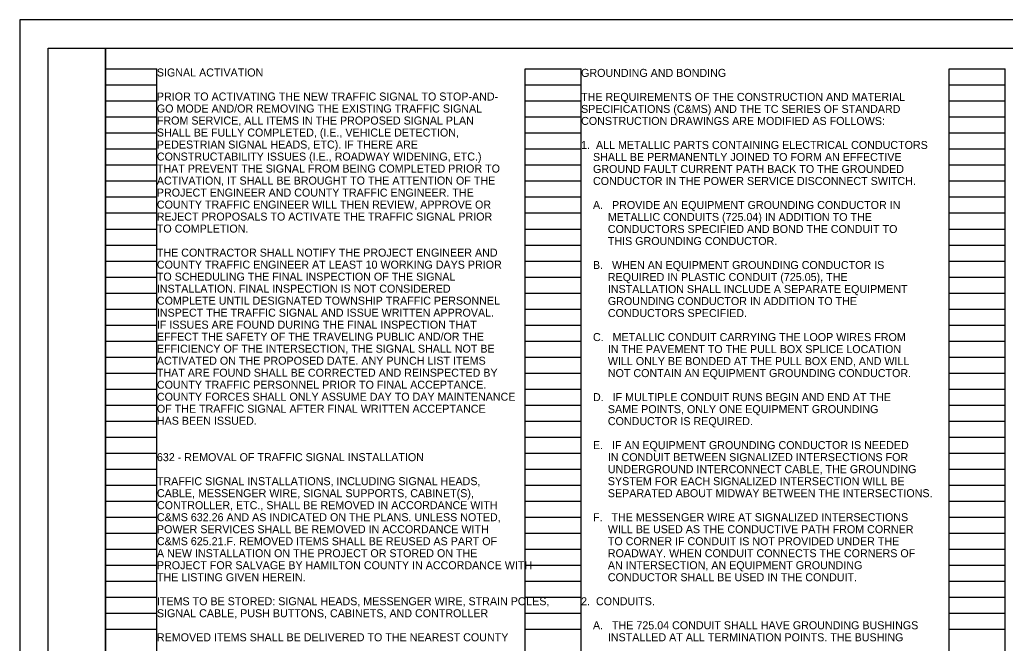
# Model space of a CAD drawing. Extents: x 0 to 34, y 0 to 22.
# Drawn here: x 0 to 17.24, y 11.1 to 22 of the extents above; entities that cross this region are included whole.
import ezdxf

# ---------------------------------------------------------------- set-up
doc = ezdxf.new("R2010")
doc.units = 0
for name, color, linetype in [('SH_Border', 7, 'Continuous'), ('SH_Cut_Line', 7, 'Continuous'), ('SH_Data', 7, 'Continuous'), ('SH_Text', 7, 'Continuous')]:
    doc.layers.add(name, color=color, linetype=linetype)

msp = doc.modelspace()

# ---------------------------------------------------------------- linework, layer by layer
at = {"layer": 'SH_Border'}
for points in [[(0.5, 21.5), (1.5, 21.5), (1.5, 0.5), (0.5, 0.5)], [(1.5, 21.5), (33.5, 21.5), (33.5, 0.5), (1.5, 0.5)]]:
    msp.add_lwpolyline(points, close=True, dxfattribs=at)
at = {"layer": 'SH_Cut_Line'}
msp.add_lwpolyline([(0, 0), (34, 0), (34, 22), (0, 22)], close=True, dxfattribs=at)
at = {"layer": 'SH_Data'}
for p, q in [((1.5, 0.98), (1.5, 21.14)), ((1.5, 21.14), (2.4, 21.14)), ((2.4, 0.98), (2.4, 21.14)), ((8.84, 0.98), (8.84, 21.14)), ((8.84, 21.14), (9.82, 21.14)), ((9.82, 0.98), (9.82, 21.14)), ((16.26, 0.98), (16.26, 21.14)), ((16.26, 21.14), (17.24, 21.14)), ((17.24, 0.98), (17.24, 21.14)), ((1.5, 20.86), (2.4, 20.86)), ((8.84, 20.86), (9.82, 20.86)), ((16.26, 20.86), (17.24, 20.86)), ((1.5, 20.58), (2.4, 20.58)), ((8.84, 20.58), (9.82, 20.58)), ((16.26, 20.58), (17.24, 20.58)), ((1.5, 20.3), (2.4, 20.3)), ((8.84, 20.3), (9.82, 20.3)), ((16.26, 20.3), (17.24, 20.3)), ((1.5, 20.02), (2.4, 20.02)), ((8.84, 20.02), (9.82, 20.02)), ((16.26, 20.02), (17.24, 20.02)), ((1.5, 19.74), (2.4, 19.74)), ((8.84, 19.74), (9.82, 19.74)), ((16.26, 19.74), (17.24, 19.74)), ((1.5, 19.46), (2.4, 19.46)), ((8.84, 19.46), (9.82, 19.46)), ((16.26, 19.46), (17.24, 19.46)), ((1.5, 19.18), (2.4, 19.18)), ((8.84, 19.18), (9.82, 19.18)), ((16.26, 19.18), (17.24, 19.18)), ((1.5, 18.9), (2.4, 18.9)), ((8.84, 18.9), (9.82, 18.9)), ((16.26, 18.9), (17.24, 18.9)), ((1.5, 18.62), (2.4, 18.62)), ((8.84, 18.62), (9.82, 18.62)), ((16.26, 18.62), (17.24, 18.62)), ((1.5, 18.34), (2.4, 18.34)), ((8.84, 18.34), (9.82, 18.34)), ((16.26, 18.34), (17.24, 18.34)), ((1.5, 18.06), (2.4, 18.06)), ((8.84, 18.06), (9.82, 18.06)), ((16.26, 18.06), (17.24, 18.06)), ((1.5, 17.78), (2.4, 17.78)), ((8.84, 17.78), (9.82, 17.78)), ((16.26, 17.78), (17.24, 17.78)), ((1.5, 17.5), (2.4, 17.5)), ((8.84, 17.5), (9.82, 17.5)), ((16.26, 17.5), (17.24, 17.5)), ((1.5, 17.22), (2.4, 17.22)), ((8.84, 17.22), (9.82, 17.22)), ((16.26, 17.22), (17.24, 17.22)), ((1.5, 16.94), (2.4, 16.94)), ((8.84, 16.94), (9.82, 16.94)), ((16.26, 16.94), (17.24, 16.94)), ((1.5, 16.66), (2.4, 16.66)), ((8.84, 16.66), (9.82, 16.66)), ((16.26, 16.66), (17.24, 16.66)), ((1.5, 16.38), (2.4, 16.38)), ((8.84, 16.38), (9.82, 16.38)), ((16.26, 16.38), (17.24, 16.38)), ((1.5, 16.1), (2.4, 16.1)), ((8.84, 16.1), (9.82, 16.1)), ((16.26, 16.1), (17.24, 16.1)), ((1.5, 15.82), (2.4, 15.82)), ((8.84, 15.82), (9.82, 15.82)), ((16.26, 15.82), (17.24, 15.82)), ((1.5, 15.54), (2.4, 15.54)), ((8.84, 15.54), (9.82, 15.54)), ((16.26, 15.54), (17.24, 15.54)), ((1.5, 15.26), (2.4, 15.26)), ((8.84, 15.26), (9.82, 15.26)), ((16.26, 15.26), (17.24, 15.26)), ((1.5, 14.98), (2.4, 14.98)), ((8.84, 14.98), (9.82, 14.98)), ((16.26, 14.98), (17.24, 14.98)), ((1.5, 14.7), (2.4, 14.7)), ((8.84, 14.7), (9.82, 14.7)), ((16.26, 14.7), (17.24, 14.7)), ((1.5, 14.42), (2.4, 14.42)), ((8.84, 14.42), (9.82, 14.42)), ((16.26, 14.42), (17.24, 14.42)), ((1.5, 14.14), (2.4, 14.14)), ((8.84, 14.14), (9.82, 14.14)), ((16.26, 14.14), (17.24, 14.14)), ((1.5, 13.86), (2.4, 13.86)), ((8.84, 13.86), (9.82, 13.86)), ((16.26, 13.86), (17.24, 13.86)), ((1.5, 13.58), (2.4, 13.58)), ((8.84, 13.58), (9.82, 13.58)), ((16.26, 13.58), (17.24, 13.58)), ((1.5, 13.3), (2.4, 13.3)), ((8.84, 13.3), (9.82, 13.3)), ((16.26, 13.3), (17.24, 13.3)), ((1.5, 13.02), (2.4, 13.02)), ((8.84, 13.02), (9.82, 13.02)), ((16.26, 13.02), (17.24, 13.02)), ((1.5, 12.74), (2.4, 12.74)), ((8.84, 12.74), (9.82, 12.74)), ((16.26, 12.74), (17.24, 12.74)), ((1.5, 12.46), (2.4, 12.46)), ((8.84, 12.46), (9.82, 12.46)), ((16.26, 12.46), (17.24, 12.46)), ((1.5, 12.18), (2.4, 12.18)), ((8.84, 12.18), (9.82, 12.18)), ((16.26, 12.18), (17.24, 12.18)), ((1.5, 11.9), (2.4, 11.9)), ((8.84, 11.9), (9.82, 11.9)), ((16.26, 11.9), (17.24, 11.9)), ((1.5, 11.62), (2.4, 11.62)), ((8.84, 11.62), (9.82, 11.62)), ((16.26, 11.62), (17.24, 11.62)), ((1.5, 11.34), (2.4, 11.34)), ((8.84, 11.34), (9.82, 11.34)), ((16.26, 11.34), (17.24, 11.34))]:
    msp.add_line(p, q, dxfattribs=at)

# ---------------------------------------------------------------- texts
at = {"layer": 'SH_Text'}
for s, p in [('SIGNAL ACTIVATION', (2.399, 21.007)), ('GROUNDING AND BONDING', (9.82, 21)), ('PRIOR TO ACTIVATING THE NEW TRAFFIC SIGNAL TO STOP-AND-', (2.399, 20.587)), ('THE REQUIREMENTS OF THE CONSTRUCTION AND MATERIAL', (9.82, 20.58)), ('GO MODE AND/OR REMOVING THE EXISTING TRAFFIC SIGNAL', (2.399, 20.377)), ('SPECIFICATIONS (C&MS) AND THE TC SERIES OF STANDARD', (9.82, 20.37)), ('FROM SERVICE, ALL ITEMS IN THE PROPOSED SIGNAL PLAN', (2.399, 20.167)), ('CONSTRUCTION DRAWINGS ARE MODIFIED AS FOLLOWS:', (9.82, 20.16)), ('SHALL BE FULLY COMPLETED, (I.E., VEHICLE DETECTION,', (2.399, 19.957)), ('PEDESTRIAN SIGNAL HEADS, ETC). IF THERE ARE', (2.399, 19.747)), ('1.  ALL METALLIC PARTS CONTAINING ELECTRICAL CONDUCTORS', (9.82, 19.74)), ('CONSTRUCTABILITY ISSUES (I.E., ROADWAY WIDENING, ETC.)', (2.399, 19.537)), ('    SHALL BE PERMANENTLY JOINED TO FORM AN EFFECTIVE', (9.82, 19.53)), ('THAT PREVENT THE SIGNAL FROM BEING COMPLETED PRIOR TO', (2.399, 19.327)), ('    GROUND FAULT CURRENT PATH BACK TO THE GROUNDED', (9.82, 19.32)), ('ACTIVATION, IT SHALL BE BROUGHT TO THE ATTENTION OF THE', (2.399, 19.117)), ('    CONDUCTOR IN THE POWER SERVICE DISCONNECT SWITCH.', (9.82, 19.11)), ('PROJECT ENGINEER AND COUNTY TRAFFIC ENGINEER. THE ', (2.399, 18.907)), ('COUNTY TRAFFIC ENGINEER WILL THEN REVIEW, APPROVE OR', (2.399, 18.697)), ('    A.   PROVIDE AN EQUIPMENT GROUNDING CONDUCTOR IN', (9.82, 18.69)), ('REJECT PROPOSALS TO ACTIVATE THE TRAFFIC SIGNAL PRIOR', (2.399, 18.487)), ('         METALLIC CONDUITS (725.04) IN ADDITION TO THE', (9.82, 18.48)), ('TO COMPLETION.', (2.399, 18.277)), ('         CONDUCTORS SPECIFIED AND BOND THE CONDUIT TO', (9.82, 18.27)), ('         THIS GROUNDING CONDUCTOR.', (9.82, 18.06)), ('THE CONTRACTOR SHALL NOTIFY THE PROJECT ENGINEER AND', (2.399, 17.857)), ('COUNTY TRAFFIC ENGINEER AT LEAST 10 WORKING DAYS PRIOR', (2.399, 17.647)), ('    B.   WHEN AN EQUIPMENT GROUNDING CONDUCTOR IS', (9.82, 17.64)), ('TO SCHEDULING THE FINAL INSPECTION OF THE SIGNAL', (2.399, 17.437)), ('         REQUIRED IN PLASTIC CONDUIT (725.05), THE', (9.82, 17.43)), ('INSTALLATION. FINAL INSPECTION IS NOT CONSIDERED', (2.399, 17.227)), ('         INSTALLATION SHALL INCLUDE A SEPARATE EQUIPMENT', (9.82, 17.22)), ('COMPLETE UNTIL DESIGNATED TOWNSHIP TRAFFIC PERSONNEL', (2.399, 17.017)), ('         GROUNDING CONDUCTOR IN ADDITION TO THE', (9.82, 17.01)), ('INSPECT THE TRAFFIC SIGNAL AND ISSUE WRITTEN APPROVAL.', (2.399, 16.807)), ('         CONDUCTORS SPECIFIED.', (9.82, 16.8)), ('IF ISSUES ARE FOUND DURING THE FINAL INSPECTION THAT', (2.399, 16.597)), ('EFFECT THE SAFETY OF THE TRAVELING PUBLIC AND/OR THE', (2.399, 16.387)), ('    C.   METALLIC CONDUIT CARRYING THE LOOP WIRES FROM', (9.82, 16.38)), ('EFFICIENCY OF THE INTERSECTION, THE SIGNAL SHALL NOT BE', (2.399, 16.177)), ('         IN THE PAVEMENT TO THE PULL BOX SPLICE LOCATION', (9.82, 16.17)), ('ACTIVATED ON THE PROPOSED DATE. ANY PUNCH LIST ITEMS', (2.399, 15.967)), ('         WILL ONLY BE BONDED AT THE PULL BOX END, AND WILL', (9.82, 15.96)), ('THAT ARE FOUND SHALL BE CORRECTED AND REINSPECTED BY', (2.399, 15.757)), ('         NOT CONTAIN AN EQUIPMENT GROUNDING CONDUCTOR.', (9.82, 15.75)), ('COUNTY TRAFFIC PERSONNEL PRIOR TO FINAL ACCEPTANCE.', (2.399, 15.547)), ('COUNTY FORCES SHALL ONLY ASSUME DAY TO DAY MAINTENANCE', (2.399, 15.337)), ('    D.   IF MULTIPLE CONDUIT RUNS BEGIN AND END AT THE', (9.82, 15.33)), ('OF THE TRAFFIC SIGNAL AFTER FINAL WRITTEN ACCEPTANCE', (2.399, 15.127)), ('         SAME POINTS, ONLY ONE EQUIPMENT GROUNDING', (9.82, 15.12)), ('HAS BEEN ISSUED.', (2.399, 14.917)), ('         CONDUCTOR IS REQUIRED.', (9.82, 14.91)), ('    E.   IF AN EQUIPMENT GROUNDING CONDUCTOR IS NEEDED', (9.82, 14.49)), ('632 - REMOVAL OF TRAFFIC SIGNAL INSTALLATION', (2.4, 14.28)), ('         IN CONDUIT BETWEEN SIGNALIZED INTERSECTIONS FOR', (9.82, 14.28)), ('         UNDERGROUND INTERCONNECT CABLE, THE GROUNDING', (9.82, 14.07)), ('TRAFFIC SIGNAL INSTALLATIONS, INCLUDING SIGNAL HEADS, ', (2.4, 13.86)), ('         SYSTEM FOR EACH SIGNALIZED INTERSECTION WILL BE', (9.82, 13.86)), ('CABLE, MESSENGER WIRE, SIGNAL SUPPORTS, CABINET(S), ', (2.4, 13.65)), ('         SEPARATED ABOUT MIDWAY BETWEEN THE INTERSECTIONS.', (9.82, 13.65)), ('CONTROLLER, ETC., SHALL BE REMOVED IN ACCORDANCE WITH ', (2.4, 13.44)), ('C&MS 632.26 AND AS INDICATED ON THE PLANS. UNLESS NOTED, ', (2.4, 13.23)), ('    F.   THE MESSENGER WIRE AT SIGNALIZED INTERSECTIONS', (9.82, 13.23)), ('POWER SERVICES SHALL BE REMOVED IN ACCORDANCE WITH ', (2.4, 13.02)), ('         WILL BE USED AS THE CONDUCTIVE PATH FROM CORNER', (9.82, 13.02)), ('C&MS 625.21.F. REMOVED ITEMS SHALL BE REUSED AS PART OF ', (2.4, 12.81)), ('         TO CORNER IF CONDUIT IS NOT PROVIDED UNDER THE', (9.82, 12.81)), ('A NEW INSTALLATION ON THE PROJECT OR STORED ON THE ', (2.4, 12.6)), ('         ROADWAY. WHEN CONDUIT CONNECTS THE CORNERS OF', (9.82, 12.6)), ('PROJECT FOR SALVAGE BY HAMILTON COUNTY IN ACCORDANCE WITH ', (2.4, 12.39)), ('         AN INTERSECTION, AN EQUIPMENT GROUNDING', (9.82, 12.39)), ('THE LISTING GIVEN HEREIN.', (2.4, 12.18)), ('         CONDUCTOR SHALL BE USED IN THE CONDUIT.', (9.82, 12.18)), ('ITEMS TO BE STORED: SIGNAL HEADS, MESSENGER WIRE, STRAIN POLES,', (2.4, 11.76)), ('2.  CONDUITS.', (9.82, 11.76)), ('SIGNAL CABLE, PUSH BUTTONS, CABINETS, AND CONTROLLER', (2.4, 11.55)), ('    A.   THE 725.04 CONDUIT SHALL HAVE GROUNDING BUSHINGS', (9.82, 11.34)), ('REMOVED ITEMS SHALL BE DELIVERED TO THE NEAREST COUNTY', (2.4, 11.13)), ('         INSTALLED AT ALL TERMINATION POINTS. THE BUSHING', (9.82, 11.13))]:
    msp.add_text(s, height=0.14, dxfattribs=at).set_placement(p)

doc.saveas('drawing.dxf')
